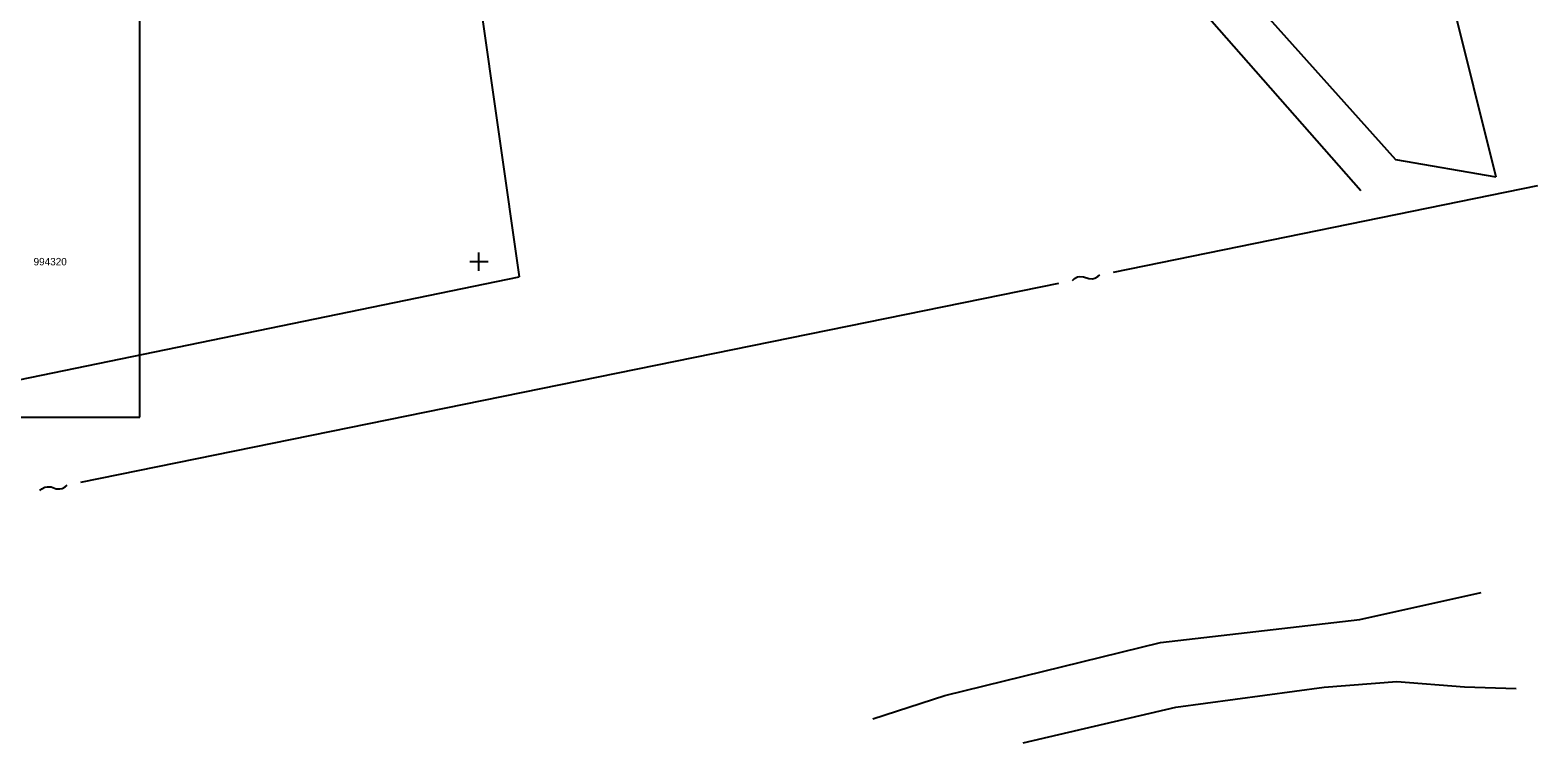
# Model space of a CAD drawing. Extents: x -651478 to -651308, y -994378 to -994071.
# Drawn here: x -651379.3 to -651314.5, y -994340.7 to -994310 of the extents above; entities that cross this region are included whole.
import ezdxf

# ---------------------------------------------------------------- set-up
doc = ezdxf.new("R2010")
doc.units = 0
for name, color, linetype in [('32_SPOJE-VEDENI', 7, 'Continuous'), ('_KM', 7, 'Continuous'), ('rezy', 7, 'Continuous'), ('ROZP', 7, 'Continuous')]:
    doc.layers.add(name, color=color, linetype=linetype)

# ---------------------------------------------------------------- blocks, each defined once
blk = doc.blocks.new('Z70')
for p, q in [((-0.4, 0), (0.4, 0)), ((0, -0.4), (0, 0.4))]:
    blk.add_line(p, q)
blk = doc.blocks.new('Z670')
for p, q in [((-0.6, 0), (-0.5, 0.06)), ((-0.5, 0.06), (-0.36, 0.1)), ((-0.36, 0.1), (-0.26, 0.1)), ((-0.26, 0.1), (-0.1, 0.06)), ((-0.1, 0.06), (0.1, -0.06)), ((0.5, -0.06), (0.6, 0)), ((0.1, -0.06), (0.26, -0.1)), ((0.26, -0.1), (0.36, -0.1)), ((0.36, -0.1), (0.5, -0.06))]:
    blk.add_line(p, q)

msp = doc.modelspace()

# ---------------------------------------------------------------- linework, layer by layer
at = {"layer": '32_SPOJE-VEDENI'}
for p, q in [((-651332.711, -994320.446), (-651314.46, -994316.73)), ((-651377.12, -994329.488), (-651335.063, -994320.925))]:
    msp.add_line(p, q, dxfattribs=at)
at = {"layer": '_KM'}
for p, q in [((-651362.49, -994291.14), (-651358.27, -994320.65)), ((-651333.54, -994301.11), (-651320.58, -994315.61)), ((-651334.39, -994302.92), (-651322.07, -994316.94)), ((-651319.37, -994303.88), (-651316.27, -994316.35)), ((-651320.58, -994315.61), (-651316.27, -994316.35)), ((-651394.04, -994328.02), (-651358.27, -994320.65)), ((-651322.12, -994335.39), (-651316.9, -994334.23)), ((-651330.69, -994336.38), (-651322.12, -994335.39)), ((-651339.96, -994338.67), (-651330.69, -994336.38)), ((-651343.06, -994339.66), (-651339.96, -994338.67)), ((-651330.03, -994339.16), (-651323.65, -994338.3)), ((-651323.65, -994338.3), (-651320.53, -994338.06)), ((-651320.53, -994338.06), (-651317.61, -994338.29)), ((-651317.61, -994338.29), (-651315.39, -994338.36)), ((-651336.59, -994340.7), (-651330.03, -994339.16))]:
    msp.add_line(p, q, dxfattribs=at)
at = {"layer": 'rezy'}
for p, q in [((-651374.583, -994326.69), (-651374.583, -994242.69)), ((-651433.983, -994326.69), (-651374.583, -994326.69))]:
    msp.add_line(p, q, dxfattribs=at)

# ---------------------------------------------------------------- block references
at = {"layer": '32_SPOJE-VEDENI', "rotation": 11.508799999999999}
for p in [(-651333.887, -994320.686), (-651378.296, -994329.728)]:
    msp.add_blockref('Z670', p, dxfattribs=at)
at = {"layer": 'ROZP'}
msp.add_blockref('Z70', (-651360, -994320), dxfattribs=at)

# ---------------------------------------------------------------- texts
msp.add_text('994320', height=0.32, dxfattribs=at).set_placement((-651379.157, -994320.16))

doc.saveas('drawing.dxf')
